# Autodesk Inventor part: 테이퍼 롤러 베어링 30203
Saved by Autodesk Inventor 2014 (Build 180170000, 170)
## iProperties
Created: 2026-07
Part Number: 테이퍼 롤러 베어링 30203
Material: 일반
Document SubType Name: Modeling
Designer: dg
Density: 1 g/cm^3
Appearance: 기본값
Author: dg
Author: jhkim
Description: 테이퍼 롤러 베어링
Creation Date: 2026-07-02
Sending System: Autodesk Inventor 2027
Preprocessor: ST-DEVELOPER v20.1
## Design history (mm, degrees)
node "테이퍼 롤러 베어링 302031"
body "Solid1"
node "Solid1_1"
node "기준1"
node "기준2"
